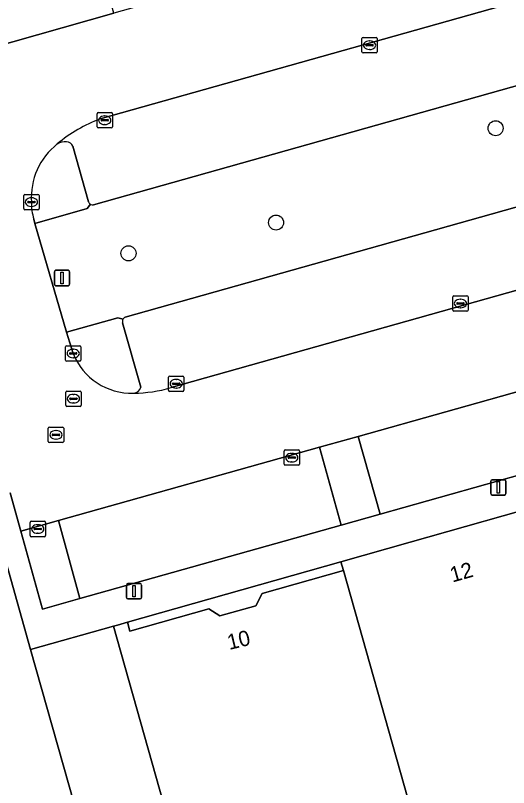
# Model space of a CAD drawing. Extents: x 159680 to 160786, y 387323 to 388340.
# Drawn here: x 159883.4 to 159915.5, y 388088.3 to 388138.6 of the extents above; entities that cross this region are included whole.
import ezdxf

# ---------------------------------------------------------------- set-up
doc = ezdxf.new("R2010")
doc.units = 0
for name, color, linetype in [('IMGEO_Berm_groen', 7, 'Continuous'), ('IMGEO_Boom', 7, 'Continuous'), ('IMGEO_Erf', 7, 'Continuous'), ('IMGEO_Kolk', 7, 'Continuous'), ('IMGEO_Lichtmast', 7, 'Continuous'), ('IMGEO_Pand', 7, 'Continuous'), ('IMGEO_Pand_nummerreeks', 7, 'Continuous'), ('IMGEO_Parkeervlak_open', 7, 'Continuous'), ('IMGEO_Rijbaan_lokaal_gesloten', 7, 'Continuous'), ('IMGEO_Rioolput', 7, 'Continuous'), ('IMGEO_Verkeerseiland_open', 7, 'Continuous'), ('IMGEO_Voetpad_open', 7, 'Continuous')]:
    doc.layers.add(name, color=color, linetype=linetype)

msp = doc.modelspace()

# ---------------------------------------------------------------- linework, layer by layer
at = {"layer": 'IMGEO_Berm_groen'}
for points in [[(159957.747, 388145.745), (159888.506, 388126.227)], [(159890.571, 388118.912), (159957.895, 388137.862)], [(159888.324, 388126.257), (159888.301, 388126.271), (159888.083, 388125.988), (159884.689, 388125.016), (159886.75, 388117.938), (159890.083, 388118.881), (159890.429, 388118.794)]]:
    msp.add_lwpolyline(points, dxfattribs=at)
for centre, radius, start, end in [((159888.459, 388126.509), 0.286, 241.8151, 279.4645), ((159890.687, 388118.628), 0.307, 112.2216, 147.2306)]:
    msp.add_arc(centre, radius, start, end, dxfattribs=at)
at = {"layer": 'IMGEO_Boom'}
for centre in [(159914.687, 388131.221), (159900.389, 388125.078), (159890.783, 388123.075)]:
    msp.add_circle(centre, 0.489, dxfattribs=at)
at = {"layer": 'IMGEO_Erf'}
msp.add_lwpolyline([(159884.404, 388097.269), (159890.447, 388075.893), (159895.849, 388077.42), (159889.796, 388098.796)], close=True, dxfattribs=at)
at = {"layer": 'IMGEO_Kolk'}
for p, q in [((159905.982, 388136.203), (159905.982, 388137.055)), ((159906.057, 388137.129), (159906.909, 388137.129)), ((159906.983, 388137.055), (159906.983, 388136.203)), ((159906.241, 388136.623), (159906.241, 388136.635)), ((159906.679, 388136.586), (159906.281, 388136.586)), ((159906.284, 388136.672), (159906.682, 388136.672)), ((159906.47, 388136.909), (159906.495, 388136.909)), ((159906.725, 388136.635), (159906.725, 388136.623)), ((159906.909, 388136.129), (159906.057, 388136.129)), ((159906.493, 388136.349), (159906.468, 388136.349)), ((159888.737, 388131.317), (159888.737, 388132.169)), ((159888.812, 388132.243), (159889.664, 388132.243)), ((159889.225, 388132.023), (159889.25, 388132.023)), ((159889.738, 388132.169), (159889.738, 388131.317)), ((159888.996, 388131.737), (159888.996, 388131.749)), ((159889.434, 388131.7), (159889.036, 388131.7)), ((159889.039, 388131.786), (159889.437, 388131.786)), ((159889.248, 388131.463), (159889.223, 388131.463)), ((159889.48, 388131.749), (159889.48, 388131.737)), ((159889.664, 388131.243), (159888.812, 388131.243)), ((159884.037, 388126.912), (159884.889, 388126.912)), ((159883.962, 388125.986), (159883.962, 388126.838)), ((159884.221, 388126.406), (159884.221, 388126.418)), ((159884.264, 388126.455), (159884.662, 388126.455)), ((159884.45, 388126.692), (159884.475, 388126.692)), ((159884.705, 388126.418), (159884.705, 388126.406)), ((159884.963, 388126.838), (159884.963, 388125.986)), ((159884.889, 388125.912), (159884.037, 388125.912)), ((159884.659, 388126.369), (159884.261, 388126.369)), ((159884.473, 388126.132), (159884.448, 388126.132)), ((159911.895, 388119.382), (159911.895, 388120.234)), ((159911.97, 388120.308), (159912.822, 388120.308)), ((159912.197, 388119.851), (159912.595, 388119.851)), ((159912.383, 388120.088), (159912.408, 388120.088)), ((159912.896, 388120.234), (159912.896, 388119.382)), ((159912.154, 388119.802), (159912.154, 388119.814)), ((159912.592, 388119.765), (159912.194, 388119.765)), ((159912.406, 388119.528), (159912.381, 388119.528)), ((159912.638, 388119.814), (159912.638, 388119.802)), ((159912.822, 388119.308), (159911.97, 388119.308)), ((159886.685, 388116.128), (159886.685, 388116.98)), ((159886.76, 388117.054), (159887.612, 388117.054)), ((159887.173, 388116.834), (159887.198, 388116.834)), ((159887.686, 388116.98), (159887.686, 388116.128)), ((159886.944, 388116.548), (159886.944, 388116.56)), ((159887.382, 388116.511), (159886.984, 388116.511)), ((159886.987, 388116.597), (159887.385, 388116.597)), ((159887.428, 388116.56), (159887.428, 388116.548)), ((159887.612, 388116.054), (159886.76, 388116.054)), ((159887.196, 388116.274), (159887.171, 388116.274)), ((159893.393, 388114.158), (159893.393, 388115.01)), ((159893.468, 388115.084), (159894.32, 388115.084)), ((159893.881, 388114.864), (159893.906, 388114.864)), ((159894.394, 388115.01), (159894.394, 388114.158)), ((159893.652, 388114.578), (159893.652, 388114.59)), ((159894.09, 388114.541), (159893.692, 388114.541)), ((159893.695, 388114.627), (159894.093, 388114.627)), ((159894.136, 388114.59), (159894.136, 388114.578)), ((159894.32, 388114.084), (159893.468, 388114.084)), ((159893.904, 388114.304), (159893.879, 388114.304)), ((159900.917, 388109.344), (159900.917, 388110.196)), ((159900.992, 388110.27), (159901.844, 388110.27)), ((159901.219, 388109.813), (159901.617, 388109.813)), ((159901.405, 388110.05), (159901.43, 388110.05)), ((159901.918, 388110.196), (159901.918, 388109.344)), ((159901.176, 388109.764), (159901.176, 388109.776)), ((159901.614, 388109.727), (159901.216, 388109.727)), ((159901.428, 388109.49), (159901.403, 388109.49)), ((159901.66, 388109.776), (159901.66, 388109.764)), ((159901.844, 388109.27), (159900.992, 388109.27)), ((159884.376, 388104.698), (159884.376, 388105.55)), ((159884.451, 388105.624), (159885.303, 388105.624)), ((159884.864, 388105.404), (159884.889, 388105.404)), ((159885.377, 388105.55), (159885.377, 388104.698)), ((159884.635, 388105.118), (159884.635, 388105.13)), ((159885.073, 388105.081), (159884.675, 388105.081)), ((159884.678, 388105.167), (159885.076, 388105.167)), ((159884.887, 388104.844), (159884.862, 388104.844)), ((159885.119, 388105.13), (159885.119, 388105.118)), ((159885.303, 388104.624), (159884.451, 388104.624))]:
    msp.add_line(p, q, dxfattribs=at)
for points in [[(159905.982, 388136.203), (159905.982, 388137.055)], [(159906.057, 388137.129), (159906.909, 388137.129)], [(159906.983, 388137.055), (159906.983, 388136.203)], [(159906.909, 388136.129), (159906.057, 388136.129)], [(159888.737, 388131.317), (159888.737, 388132.169)], [(159888.812, 388132.243), (159889.664, 388132.243)], [(159889.738, 388132.169), (159889.738, 388131.317)], [(159889.664, 388131.243), (159888.812, 388131.243)], [(159884.037, 388126.912), (159884.889, 388126.912)], [(159883.962, 388125.986), (159883.962, 388126.838)], [(159884.963, 388126.838), (159884.963, 388125.986)], [(159884.889, 388125.912), (159884.037, 388125.912)], [(159911.895, 388119.382), (159911.895, 388120.234)], [(159911.97, 388120.308), (159912.822, 388120.308)], [(159912.896, 388120.234), (159912.896, 388119.382)], [(159912.822, 388119.308), (159911.97, 388119.308)], [(159886.685, 388116.128), (159886.685, 388116.98)], [(159886.76, 388117.054), (159887.612, 388117.054)], [(159887.686, 388116.98), (159887.686, 388116.128)], [(159887.612, 388116.054), (159886.76, 388116.054)], [(159893.393, 388114.158), (159893.393, 388115.01)], [(159893.468, 388115.084), (159894.32, 388115.084)], [(159894.394, 388115.01), (159894.394, 388114.158)], [(159894.32, 388114.084), (159893.468, 388114.084)], [(159900.917, 388109.344), (159900.917, 388110.196)], [(159900.992, 388110.27), (159901.844, 388110.27)], [(159901.918, 388110.196), (159901.918, 388109.344)], [(159901.844, 388109.27), (159900.992, 388109.27)], [(159884.376, 388104.698), (159884.376, 388105.55)], [(159884.451, 388105.624), (159885.303, 388105.624)], [(159885.377, 388105.55), (159885.377, 388104.698)], [(159885.303, 388104.624), (159884.451, 388104.624)]]:
    msp.add_lwpolyline(points, dxfattribs=at)
for centre, radius, start, end in [((159906.059, 388137.053), 0.0765, 91.552, 178.448), ((159906.059, 388137.053), 0.0765, 91.552, 178.448), ((159906.907, 388137.053), 0.0765, 1.552, 88.448), ((159906.907, 388137.053), 0.0765, 1.552, 88.448), ((159906.281, 388136.632), 0.0403, 85.8775, 175.7526), ((159906.278, 388136.622), 0.0366, 178.938, 274.7102), ((159906.682, 388136.629), 0.043, 264.8664, 352.4533), ((159906.686, 388136.634), 0.0386, 1.7309, 96.639), ((159906.059, 388136.205), 0.0765, 181.552, 268.448), ((159906.059, 388136.205), 0.0765, 181.552, 268.448), ((159906.907, 388136.205), 0.0765, 271.552, 358.448), ((159906.907, 388136.205), 0.0765, 271.552, 358.448), ((159888.814, 388132.167), 0.0765, 91.552, 178.448), ((159888.814, 388132.167), 0.0765, 91.552, 178.448), ((159889.662, 388132.167), 0.0765, 1.552, 88.448), ((159889.662, 388132.167), 0.0765, 1.552, 88.448), ((159889.036, 388131.746), 0.0403, 85.8775, 175.7526), ((159889.033, 388131.736), 0.0366, 178.938, 274.7102), ((159889.437, 388131.743), 0.043, 264.8664, 352.4533), ((159889.441, 388131.748), 0.0386, 1.7309, 96.639), ((159888.814, 388131.319), 0.0765, 181.552, 268.448), ((159888.814, 388131.319), 0.0765, 181.552, 268.448), ((159889.662, 388131.319), 0.0765, 271.552, 358.448), ((159889.662, 388131.319), 0.0765, 271.552, 358.448), ((159884.039, 388126.836), 0.0765, 91.552, 178.448), ((159884.039, 388126.836), 0.0765, 91.552, 178.448), ((159884.887, 388126.836), 0.0765, 1.552, 88.448), ((159884.887, 388126.836), 0.0765, 1.552, 88.448), ((159884.261, 388126.415), 0.0403, 85.8775, 175.7526), ((159884.258, 388126.405), 0.0366, 178.938, 274.7102), ((159884.662, 388126.412), 0.043, 264.8664, 352.4533), ((159884.666, 388126.417), 0.0386, 1.7309, 96.639), ((159884.039, 388125.988), 0.0765, 181.552, 268.448), ((159884.039, 388125.988), 0.0765, 181.552, 268.448), ((159884.887, 388125.988), 0.0765, 271.552, 358.448), ((159884.887, 388125.988), 0.0765, 271.552, 358.448), ((159911.972, 388120.232), 0.0765, 91.552, 178.448), ((159911.972, 388120.232), 0.0765, 91.552, 178.448), ((159912.194, 388119.811), 0.0403, 85.8775, 175.7526), ((159912.599, 388119.813), 0.0386, 1.7309, 96.639), ((159912.82, 388120.232), 0.0765, 1.552, 88.448), ((159912.82, 388120.232), 0.0765, 1.552, 88.448), ((159911.972, 388119.384), 0.0765, 181.552, 268.448), ((159911.972, 388119.384), 0.0765, 181.552, 268.448), ((159912.191, 388119.801), 0.0366, 178.938, 274.7102), ((159912.595, 388119.808), 0.043, 264.8664, 352.4533), ((159912.82, 388119.384), 0.0765, 271.552, 358.448), ((159912.82, 388119.384), 0.0765, 271.552, 358.448), ((159886.762, 388116.978), 0.0765, 91.552, 178.448), ((159886.762, 388116.978), 0.0765, 91.552, 178.448), ((159887.61, 388116.978), 0.0765, 1.552, 88.448), ((159887.61, 388116.978), 0.0765, 1.552, 88.448), ((159886.984, 388116.557), 0.0403, 85.8775, 175.7526), ((159886.981, 388116.547), 0.0366, 178.938, 274.7102), ((159887.385, 388116.554), 0.043, 264.8664, 352.4533), ((159887.389, 388116.559), 0.0386, 1.7309, 96.639), ((159886.762, 388116.13), 0.0765, 181.552, 268.448), ((159886.762, 388116.13), 0.0765, 181.552, 268.448), ((159887.61, 388116.13), 0.0765, 271.552, 358.448), ((159887.61, 388116.13), 0.0765, 271.552, 358.448), ((159893.47, 388115.008), 0.0765, 91.552, 178.448), ((159893.47, 388115.008), 0.0765, 91.552, 178.448), ((159894.318, 388115.008), 0.0765, 1.552, 88.448), ((159894.318, 388115.008), 0.0765, 1.552, 88.448), ((159893.692, 388114.587), 0.0403, 85.8775, 175.7526), ((159893.689, 388114.577), 0.0366, 178.938, 274.7102), ((159894.093, 388114.584), 0.043, 264.8664, 352.4533), ((159894.097, 388114.589), 0.0386, 1.7309, 96.639), ((159893.47, 388114.16), 0.0765, 181.552, 268.448), ((159893.47, 388114.16), 0.0765, 181.552, 268.448), ((159894.318, 388114.16), 0.0765, 271.552, 358.448), ((159894.318, 388114.16), 0.0765, 271.552, 358.448), ((159900.994, 388110.194), 0.0765, 91.552, 178.448), ((159900.994, 388110.194), 0.0765, 91.552, 178.448), ((159901.216, 388109.773), 0.0403, 85.8775, 175.7526), ((159901.621, 388109.775), 0.0386, 1.7309, 96.639), ((159901.842, 388110.194), 0.0765, 1.552, 88.448), ((159901.842, 388110.194), 0.0765, 1.552, 88.448), ((159900.994, 388109.346), 0.0765, 181.552, 268.448), ((159900.994, 388109.346), 0.0765, 181.552, 268.448), ((159901.213, 388109.763), 0.0366, 178.938, 274.7102), ((159901.617, 388109.77), 0.043, 264.8664, 352.4533), ((159901.842, 388109.346), 0.0765, 271.552, 358.448), ((159901.842, 388109.346), 0.0765, 271.552, 358.448), ((159884.453, 388105.548), 0.0765, 91.552, 178.448), ((159884.453, 388105.548), 0.0765, 91.552, 178.448), ((159885.301, 388105.548), 0.0765, 1.552, 88.448), ((159885.301, 388105.548), 0.0765, 1.552, 88.448), ((159884.675, 388105.127), 0.0403, 85.8775, 175.7526), ((159884.672, 388105.117), 0.0366, 178.938, 274.7102), ((159885.076, 388105.124), 0.043, 264.8664, 352.4533), ((159885.08, 388105.129), 0.0386, 1.7309, 96.639), ((159884.453, 388104.7), 0.0765, 181.552, 268.448), ((159884.453, 388104.7), 0.0765, 181.552, 268.448), ((159885.301, 388104.7), 0.0765, 271.552, 358.448), ((159885.301, 388104.7), 0.0765, 271.552, 358.448)]:
    msp.add_arc(centre, radius, start, end, dxfattribs=at)
for centre, major_axis, ratio, start_param, end_param in [((159906.469, 388136.629), (-0.387, 0.002), 0.722429, 4.712389, 7.853982), ((159906.494, 388136.629), (-0.39, 0.002), 0.717154, 1.570796, 4.712389), ((159889.224, 388131.743), (-0.387, 0.002), 0.722429, 4.712389, 7.853982), ((159889.249, 388131.743), (-0.39, 0.002), 0.717154, 1.570796, 4.712389), ((159884.449, 388126.412), (-0.387, 0.002), 0.722429, 4.712389, 7.853982), ((159884.474, 388126.412), (-0.39, 0.002), 0.717154, 1.570796, 4.712389), ((159912.382, 388119.808), (-0.387, 0.002), 0.722429, 4.712389, 7.853982), ((159912.407, 388119.808), (-0.39, 0.002), 0.717154, 1.570796, 4.712389), ((159887.172, 388116.554), (-0.387, 0.002), 0.722429, 4.712389, 7.853982), ((159887.197, 388116.554), (-0.39, 0.002), 0.717154, 1.570796, 4.712389), ((159893.88, 388114.584), (-0.387, 0.002), 0.722429, 4.712389, 7.853982), ((159893.905, 388114.584), (-0.39, 0.002), 0.717154, 1.570796, 4.712389), ((159901.404, 388109.77), (-0.387, 0.002), 0.722429, 4.712389, 7.853982), ((159901.429, 388109.77), (-0.39, 0.002), 0.717154, 1.570796, 4.712389), ((159884.863, 388105.124), (-0.387, 0.002), 0.722429, 4.712389, 7.853982), ((159884.888, 388105.124), (-0.39, 0.002), 0.717154, 1.570796, 4.712389)]:
    msp.add_ellipse(centre, major_axis=major_axis, ratio=ratio, start_param=start_param, end_param=end_param, dxfattribs=at)
at = {"layer": 'IMGEO_Lichtmast'}
for p, q in [((159885.955, 388121.068), (159885.955, 388121.868)), ((159885.955, 388121.868), (159885.955, 388121.068)), ((159886.055, 388121.968), (159886.845, 388121.968)), ((159886.845, 388121.968), (159886.055, 388121.968)), ((159886.945, 388121.868), (159886.945, 388121.068)), ((159886.945, 388121.068), (159886.945, 388121.868)), ((159886.845, 388120.968), (159886.055, 388120.968)), ((159886.055, 388120.968), (159886.845, 388120.968)), ((159914.472, 388108.334), (159915.262, 388108.334)), ((159915.262, 388108.334), (159914.472, 388108.334)), ((159914.372, 388107.434), (159914.372, 388108.234)), ((159914.372, 388108.234), (159914.372, 388107.434)), ((159915.362, 388108.234), (159915.362, 388107.434)), ((159915.362, 388107.434), (159915.362, 388108.234)), ((159915.262, 388107.334), (159914.472, 388107.334)), ((159914.472, 388107.334), (159915.262, 388107.334)), ((159890.647, 388100.673), (159890.647, 388101.473)), ((159890.647, 388101.473), (159890.647, 388100.673)), ((159890.747, 388101.573), (159891.537, 388101.573)), ((159891.537, 388101.573), (159890.747, 388101.573)), ((159891.637, 388101.473), (159891.637, 388100.673)), ((159891.637, 388100.673), (159891.637, 388101.473)), ((159891.537, 388100.573), (159890.747, 388100.573)), ((159890.747, 388100.573), (159891.537, 388100.573))]:
    msp.add_line(p, q, dxfattribs=at)
for points in [[(159886.375, 388121.843), (159886.525, 388121.843), (159886.525, 388121.093), (159886.375, 388121.093), (159886.375, 388121.843)], [(159914.792, 388108.209), (159914.942, 388108.209), (159914.942, 388107.459), (159914.792, 388107.459), (159914.792, 388108.209)], [(159891.067, 388101.448), (159891.217, 388101.448), (159891.217, 388100.698), (159891.067, 388100.698), (159891.067, 388101.448)]]:
    msp.add_lwpolyline(points, dxfattribs=at)
for centre, start, end in [((159886.055, 388121.868), 90, 180), ((159886.055, 388121.868), 90, 180), ((159886.845, 388121.868), 0, 90), ((159886.845, 388121.868), 360, 90), ((159886.055, 388121.068), 180, 270), ((159886.055, 388121.068), 180, 270), ((159886.845, 388121.068), 270, 0), ((159886.845, 388121.068), 270, 0), ((159914.472, 388108.234), 90, 180), ((159914.472, 388108.234), 90, 180), ((159915.262, 388108.234), 0, 90), ((159915.262, 388108.234), 360, 90), ((159914.472, 388107.434), 180, 270), ((159914.472, 388107.434), 180, 270), ((159915.262, 388107.434), 270, 0), ((159915.262, 388107.434), 270, 0), ((159890.747, 388101.473), 90, 180), ((159890.747, 388101.473), 90, 180), ((159891.537, 388101.473), 0, 90), ((159891.537, 388101.473), 360, 90), ((159890.747, 388100.673), 180, 270), ((159890.747, 388100.673), 180, 270), ((159891.537, 388100.673), 270, 0), ((159891.537, 388100.673), 270, 0)]:
    msp.add_arc(centre, 0.1, start, end, dxfattribs=at)
at = {"layer": 'IMGEO_Pand'}
for points in [[(159904.613, 388102.991), (159904.776, 388102.414), (159908.978, 388087.576), (159916.983, 388059.308), (159931.133, 388063.304), (159924.324, 388087.35), (159923.128, 388091.583), (159918.907, 388106.514), (159918.772, 388106.993), (159909.131, 388104.268)], [(159865.52, 388101.823), (159880.352, 388048.965), (159896.75, 388053.596), (159890.447, 388075.893), (159884.404, 388097.269), (159881.815, 388106.429), (159876.836, 388105.022)], [(159889.796, 388098.796), (159895.849, 388077.42), (159890.447, 388075.893), (159896.75, 388053.596), (159916.983, 388059.308), (159908.978, 388087.576), (159904.776, 388102.414), (159899.486, 388100.916), (159899.085, 388100.128), (159896.728, 388099.46), (159896.022, 388099.935), (159890.874, 388098.478), (159890.71, 388099.055), (159890.058, 388098.87)]]:
    msp.add_lwpolyline(points, close=True, dxfattribs=at)
at = {"layer": 'IMGEO_Parkeervlak_open'}
for points in [[(159954.712, 388150.359), (159888.947, 388131.828)], [(159888.506, 388126.227), (159957.747, 388145.745)], [(159959.866, 388138.426), (159957.895, 388137.862), (159890.571, 388118.912)], [(159893.564, 388114.331), (159958.725, 388132.684), (159959.853, 388133.046)], [(159887.162, 388130.055), (159888.187, 388126.422)], [(159888.301, 388126.271), (159888.324, 388126.257)], [(159890.391, 388118.559), (159891.594, 388114.357)]]:
    msp.add_lwpolyline(points, dxfattribs=at)
for points in [[(159888.37, 388143.784), (159883.937, 388142.537), (159873.898, 388139.724), (159875.381, 388134.615), (159879.868, 388135.898), (159889.835, 388138.706)], [(159922.67, 388115.909), (159917.152, 388114.356), (159905.738, 388111.152), (159907.177, 388106.094), (159924.119, 388110.86)], [(159903.22, 388110.445), (159886.219, 388105.673), (159887.608, 388100.589), (159904.639, 388105.38)]]:
    msp.add_lwpolyline(points, close=True, dxfattribs=at)
for centre, radius, start, end in [((159892.139, 388123.142), 9.254, 110.1759, 130.3446), ((159886.635, 388129.484), 0.861, 81.8937, 124.3982), ((159886.73, 388129.866), 0.472, 23.6402, 86.7935), ((159888.459, 388126.509), 0.286, 197.7351, 236.3681), ((159888.459, 388126.509), 0.286, 241.8151, 279.4645), ((159890.687, 388118.628), 0.307, 112.2216, 147.2306), ((159890.686, 388118.632), 0.304, 147.7823, 193.847), ((159891.105, 388114.479), 0.504, 270.8794, 346.0323), ((159891.14, 388122.404), 8.429, 269.8165, 286.712)]:
    msp.add_arc(centre, radius, start, end, dxfattribs=at)
at = {"layer": 'IMGEO_Rijbaan_lokaal_gesloten'}
for points in [[(159965.053, 388157.412), (159964.443, 388159.728), (159955.7, 388157.265), (159950.73, 388155.864), (159948.403, 388155.209), (159941.032, 388153.132), (159936.232, 388151.779), (159931.275, 388150.383), (159899.607, 388141.46), (159889.835, 388138.706), (159879.868, 388135.898), (159875.381, 388134.615), (159875.587, 388133.905), (159876.027, 388132.386)], [(159888.947, 388131.828), (159954.712, 388150.359)], [(159959.853, 388133.046), (159958.725, 388132.684), (159893.564, 388114.331)], [(159883.068, 388107.488), (159883.776, 388104.987), (159886.219, 388105.673), (159903.22, 388110.445), (159905.738, 388111.152), (159917.152, 388114.356), (159922.67, 388115.909), (159934.971, 388119.371), (159952.551, 388124.319), (159959.327, 388126.241), (159972.859, 388130.08), (159972.326, 388132.105)], [(159887.186, 388116.554), (159886.75, 388117.938), (159884.689, 388125.016), (159884.628, 388125.302)]]:
    msp.add_lwpolyline(points, dxfattribs=at)
for centre, radius, start, end in [((159892.139, 388123.142), 9.254, 110.1759, 130.3446), ((159888.899, 388126.703), 4.445, 128.2295, 183.7528), ((159887.359, 388126.275), 2.899, 177.294, 199.616), ((159890.957, 388118.017), 4.045, 201.2032, 272.2081), ((159891.14, 388122.404), 8.429, 269.8165, 286.712)]:
    msp.add_arc(centre, radius, start, end, dxfattribs=at)
at = {"layer": 'IMGEO_Rioolput'}
for p, q in [((159886.7, 388113.183), (159886.7, 388114.035)), ((159886.775, 388114.109), (159887.627, 388114.109)), ((159887.188, 388113.889), (159887.213, 388113.889)), ((159887.701, 388114.035), (159887.701, 388113.183)), ((159886.959, 388113.603), (159886.959, 388113.615)), ((159887.397, 388113.566), (159886.999, 388113.566)), ((159887.002, 388113.652), (159887.4, 388113.652)), ((159887.211, 388113.329), (159887.186, 388113.329)), ((159887.443, 388113.615), (159887.443, 388113.603)), ((159887.627, 388113.109), (159886.775, 388113.109)), ((159885.561, 388110.83), (159885.561, 388111.682)), ((159885.636, 388111.756), (159886.488, 388111.756)), ((159885.863, 388111.299), (159886.261, 388111.299)), ((159886.049, 388111.536), (159886.074, 388111.536)), ((159886.562, 388111.682), (159886.562, 388110.83)), ((159885.82, 388111.25), (159885.82, 388111.262)), ((159886.258, 388111.213), (159885.86, 388111.213)), ((159886.072, 388110.976), (159886.047, 388110.976)), ((159886.304, 388111.262), (159886.304, 388111.25)), ((159886.488, 388110.756), (159885.636, 388110.756))]:
    msp.add_line(p, q, dxfattribs=at)
for points in [[(159886.7, 388113.183), (159886.7, 388114.035)], [(159886.775, 388114.109), (159887.627, 388114.109)], [(159887.701, 388114.035), (159887.701, 388113.183)], [(159887.627, 388113.109), (159886.775, 388113.109)], [(159885.561, 388110.83), (159885.561, 388111.682)], [(159885.636, 388111.756), (159886.488, 388111.756)], [(159886.562, 388111.682), (159886.562, 388110.83)], [(159886.488, 388110.756), (159885.636, 388110.756)]]:
    msp.add_lwpolyline(points, dxfattribs=at)
for centre, radius, start, end in [((159886.777, 388114.033), 0.0765, 91.552, 178.448), ((159886.777, 388114.033), 0.0765, 91.552, 178.448), ((159887.625, 388114.033), 0.0765, 1.552, 88.448), ((159887.625, 388114.033), 0.0765, 1.552, 88.448), ((159886.999, 388113.612), 0.0403, 85.8775, 175.7526), ((159886.996, 388113.602), 0.0366, 178.938, 274.7102), ((159887.4, 388113.609), 0.043, 264.8664, 352.4533), ((159887.404, 388113.614), 0.0386, 1.7309, 96.639), ((159886.777, 388113.185), 0.0765, 181.552, 268.448), ((159886.777, 388113.185), 0.0765, 181.552, 268.448), ((159887.625, 388113.185), 0.0765, 271.552, 358.448), ((159887.625, 388113.185), 0.0765, 271.552, 358.448), ((159885.638, 388111.68), 0.0765, 91.552, 178.448), ((159885.638, 388111.68), 0.0765, 91.552, 178.448), ((159885.86, 388111.259), 0.0403, 85.8775, 175.7526), ((159886.265, 388111.261), 0.0386, 1.7309, 96.639), ((159886.486, 388111.68), 0.0765, 1.552, 88.448), ((159886.486, 388111.68), 0.0765, 1.552, 88.448), ((159885.638, 388110.832), 0.0765, 181.552, 268.448), ((159885.638, 388110.832), 0.0765, 181.552, 268.448), ((159885.857, 388111.249), 0.0366, 178.938, 274.7102), ((159886.261, 388111.256), 0.043, 264.8664, 352.4533), ((159886.486, 388110.832), 0.0765, 271.552, 358.448), ((159886.486, 388110.832), 0.0765, 271.552, 358.448)]:
    msp.add_arc(centre, radius, start, end, dxfattribs=at)
for centre, major_axis, ratio, start_param, end_param in [((159887.187, 388113.609), (-0.387, 0.002), 0.722429, 4.712389, 7.853982), ((159887.212, 388113.609), (-0.39, 0.002), 0.717154, 1.570796, 4.712389), ((159886.048, 388111.256), (-0.387, 0.002), 0.722429, 4.712389, 7.853982), ((159886.073, 388111.256), (-0.39, 0.002), 0.717154, 1.570796, 4.712389)]:
    msp.add_ellipse(centre, major_axis=major_axis, ratio=ratio, start_param=start_param, end_param=end_param, dxfattribs=at)
at = {"layer": 'IMGEO_Verkeerseiland_open'}
for points in [[(159888.187, 388126.422), (159887.162, 388130.055)], [(159884.628, 388125.302), (159884.689, 388125.016), (159888.083, 388125.988), (159888.301, 388126.271)], [(159890.429, 388118.794), (159890.083, 388118.881), (159886.75, 388117.938), (159887.186, 388116.554)], [(159891.594, 388114.357), (159890.391, 388118.559)]]:
    msp.add_lwpolyline(points, dxfattribs=at)
for centre, radius, start, end in [((159888.899, 388126.703), 4.445, 128.2295, 183.7528), ((159886.635, 388129.484), 0.861, 81.8937, 124.3982), ((159886.73, 388129.866), 0.472, 23.6402, 86.7935), ((159887.359, 388126.275), 2.899, 177.294, 199.616), ((159888.459, 388126.509), 0.286, 197.7351, 236.3681), ((159890.686, 388118.632), 0.304, 147.7823, 193.847), ((159890.957, 388118.017), 4.045, 201.2032, 272.2081), ((159891.105, 388114.479), 0.504, 270.8794, 346.0323)]:
    msp.add_arc(centre, radius, start, end, dxfattribs=at)
at = {"layer": 'IMGEO_Voetpad_open'}
for points in [[(159972.326, 388132.105), (159972.859, 388130.08), (159974.309, 388125), (159971.667, 388124.235), (159960.818, 388121.183), (159936.4, 388114.314), (159924.119, 388110.86), (159907.177, 388106.094), (159904.639, 388105.38), (159887.608, 388100.589), (159885.182, 388099.907), (159883.776, 388104.987), (159883.068, 388107.488)], [(159876.836, 388105.022), (159881.815, 388106.429), (159884.404, 388097.269), (159889.796, 388098.796), (159890.058, 388098.87), (159890.71, 388099.055), (159904.613, 388102.991), (159909.131, 388104.268), (159918.772, 388106.993), (159924.23, 388108.535), (159925.692, 388108.945), (159929.739, 388110.084), (159932.894, 388110.974), (159937.772, 388112.349), (159950.525, 388115.944), (159955.427, 388117.326), (159961.828, 388119.131), (159967.514, 388120.734), (159976.338, 388123.222)]]:
    msp.add_lwpolyline(points, dxfattribs=at)
for points in [[(159905.738, 388111.152), (159903.22, 388110.445), (159904.639, 388105.38), (159907.177, 388106.094)], [(159886.219, 388105.673), (159883.776, 388104.987), (159885.182, 388099.907), (159887.608, 388100.589)], [(159904.613, 388102.991), (159890.71, 388099.055), (159890.874, 388098.478), (159896.022, 388099.935), (159896.728, 388099.46), (159899.085, 388100.128), (159899.486, 388100.916), (159904.776, 388102.414)]]:
    msp.add_lwpolyline(points, close=True, dxfattribs=at)

# ---------------------------------------------------------------- texts
at = {"layer": 'IMGEO_Pand_nummerreeks'}
for s, rotation, p in [('12', 15.7828, (159911.874, 388101.634)), ('10', 13.5782, (159897.345, 388097.245))]:
    msp.add_text(s, height=1, rotation=rotation, dxfattribs=at).set_placement(p)

doc.saveas('drawing.dxf')
